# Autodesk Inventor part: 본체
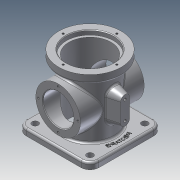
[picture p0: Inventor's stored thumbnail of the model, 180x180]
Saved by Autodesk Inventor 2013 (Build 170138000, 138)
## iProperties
Created: 2021-03
Part Number: 본체
Material: 알루미늄 6061
Document SubType Name: Modeling
Designer: a
Density: 2.71 g/cm^3
Mass: 833.809 g
Surface Area: 863.886 cm^2
Volume: 307.678 cm^3
Author: a
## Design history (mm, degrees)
sketch "스케치2"
  geometry: L1 (0, 55.5)-(0, -55.5); L2 (0, 55.5)-(-38, 55.5); L3 (-38, 55.5)-(-38, -55.5); L4 (-38, -55.5)-(0, -55.5); 2 further points
  constraints: 8 end point, 3 perpendicular, 1 coincident, 1 midpoint, 1 vertical
  dimensions: "d2" = 111 distance of L1.start L1.end; "d3" = 38 distance of L1.start L2.end
revolve "회전1" sketch "스케치2" stored, may be unused: angle "d4" = 90 deg
sketch "스케치3"
  geometry: C1 r 38 at (0, 0) reference; 1 further point
  constraints: 1 coincident
hole "구멍1" sketch "스케치3" at (0, 0) diameter "d5" = 66; stored, may be unused: countersink angle "d9" = 90 deg, drill point angle "d11" = 118 deg; dims "d6" = 6, "d7" = 74, "d8" = 7, "d10" = 8
sketch "스케치4"
  geometry: C1 r 38 at (0, 0) reference; C2 r 49 at (0, 0)
  constraints: 1 centre point, 1 coincident
  dimensions: "d12" = 98 diameter of C2
extrude "돌출1" join sketch "스케치4" distance "d13" = 13; taper "d14" = 0 deg
node "작업 평면1"
sketch "스케치6"
  geometry: L1 (38, -55.5)-(-38, -55.5) reference; L2 (0, -55.5)-(0, -1.5); C1 r 35 at (0, -1.5); 1 further point
  constraints: 2 end point, 1 centre point, 1 coincident, 1 midpoint, 1 perpendicular
  dimensions: "d88" = 54 distance of L2.start L2.end; "d89" = 70 diameter of C1
extrude "돌출2" join sketch "스케치6" stored distance "d17" = 13; taper "d18" = 0 deg
sketch "스케치9"
  geometry: L1 (43, -57)-(-43, -57); L2 (-57, -43)-(-57, 43); L3 (-43, 57)-(43, 57); L4 (57, 43)-(57, -43); L5 (57, -57)-(-57, 57); L6 (-57, -57)-(57, 57); C1 r 38 at (0, 0) reference; A1 r 14 centre (-43, 43) between (-43, 57) and (-57, 43); A2 r 14 centre (43, 43) between (57, 43) and (43, 57); A3 r 14 centre (-43, -43) between (-57, -43) and (-43, -57); A4 r 14 centre (43, -43) between (43, -57) and (57, -43)
  constraints: 12 end point, 8 point on circle, 8 point on line, 8 tangent, 4 centre point, 3 equal radius, 2 midpoint, 2 parallel, 1 horizontal, 1 perpendicular
  dimensions: "d34" = 114 distance of L5.end L6.end; "d35" = 114 distance of L6.start L5.end; "d36" = 14 radius of A1
extrude "돌출4" join sketch "스케치9" distance "d37" = 10; taper "d38" = 0 deg
sketch "스케치10"
  geometry: A1 r 14 centre (43, -43) between (43, -57) and (57, -43) reference; A2 r 14 centre (43, 43) between (57, 43) and (43, 57) reference; A3 r 14 centre (-43, 43) between (-43, 57) and (-57, 43) reference; A4 r 14 centre (-43, -43) between (-57, -43) and (-43, -57) reference; 4 further points
  constraints: 4 coincident
hole "구멍3" sketch "스케치10" at (-43, 43), (43, 43), (43, -43), (-43, -43) diameter "d39" = 10; stored, may be unused: countersink angle "d43" = 90 deg, drill point angle "d45" = 0 deg; dims "d40" = 6, "d41" = 74, "d42" = 7, "d44" = 8
node "작업 평면3"
sketch "스케치11"
  geometry: L1 (-14.5, -7)-(14.5, -7); L2 (14.5, -7)-(14.5, 7); L3 (14.5, 7)-(-14.5, 7); L4 (-14.5, 7)-(-14.5, -7); L5 (-14.5, -7)-(14.5, 7); L6 (14.5, -7)-(-14.5, 7); 1 further point
  constraints: 12 end point, 2 midpoint, 2 parallel, 1 horizontal, 1 perpendicular
  dimensions: "d50" = 29 distance of L3.end L2.end; "d52" = 14 distance of L1.end L2.end
extrude "돌출5" join sketch "스케치11" stored distance "d53" = 10; taper "d54" = 0 deg
feature "면 기울기1" dims angle "d55" = 15 deg
feature "면 기울기2" dims angle "d56" = 15 deg
sketch "스케치12"
  geometry: L1 (7, 14.5)-(-7, 14.5) reference; L2 (-7, -14.5)-(7, -14.5) reference; 3 further points
  constraints: 2 horizontal alignment, 2 midpoint, 4 other
extrude "돌출6" join sketch "스케치12" stored distance "d61" = 0; taper "d62" = 15 deg
sketch "스케치13"
  geometry: A1 r 7 centre (0, -14.5) between (-7, -14.5) and (7, -14.5) reference; A2 r 7 centre (0, 14.5) between (7, 14.5) and (-7, 14.5) reference; 3 further points
  constraints: 2 coincident
hole "구멍4" sketch "스케치13" at (0, 14.5), (0, -14.5) diameter "d63" = 4.134; stored, may be unused: countersink angle "d67" = 90 deg, drill point angle "d69" = 118 deg; dims "d64" = 8, "d65" = 74, "d66" = 7, "d68" = 10
sketch "스케치14"
  geometry: L1 (0, 0)-(0, 42); C1 r 37 at (0, 0) reference; 1 further point
  constraints: 2 end point, 1 coincident, 1 vertical
  dimensions: "d70" = 42 distance of L1.start L1.end
hole "구멍5" sketch "스케치14" at (0, 42) diameter "d71" = 3.242; stored, may be unused: countersink angle "d75" = 90 deg, drill point angle "d77" = 118 deg; dims "d72" = 6, "d73" = 74, "d74" = 7, "d76" = 8
fillet "모깎기1" dims "d81" = 3
chamfer "모따기1" distance "d82" = 1; stored, may be unused: second distance "d83" = 2, angle "d84" = 45 deg
sketch "스케치15"
  geometry: C1 r 41 at (0, 0) reference; C2 r 50 at (0, 0)
  constraints: 1 centre point, 1 coincident, 1 other
  dimensions: "d85" = 100 diameter of C2
feature "엠보싱1" sketch "스케치15" dims "d18" = 0, "d86" = 0.5, "d87" = 0
sketch "스케치16"
  geometry: L1 (0, 0)-(0, 31); C1 r 35 at (0, 0) reference; 2 further points
  constraints: 2 end point, 1 coincident, 1 vertical
  dimensions: "d90" = 31 distance of L1.start L1.end
hole "구멍6" sketch "스케치16" at (0, 31) diameter "d91" = 3.242; stored, may be unused: countersink angle "d95" = 90 deg, drill point angle "d97" = 118 deg; dims "d92" = 6, "d93" = 74, "d94" = 7, "d96" = 8
sketch "스케치17"
  geometry: C1 r 35 at (0, 0) reference; C2 r 24 at (0, 0); 1 further point
  constraints: 1 centre point, 1 coincident
  dimensions: "d101" = 48 diameter of C2
extrude "돌출7" cut sketch "스케치17" stored distance "d102" = 10; taper "d103" = 0 deg
chamfer "모따기2" distance "d104" = 1; stored, may be unused: second distance "d105" = 2, angle "d106" = 45 deg
fillet "모깎기2" dims "d107" = 3
node "솔리드1"
mirror "대칭1"
pattern_circular "원형 패턴2" dims angle "d79" = 360 deg
pattern_circular "원형 패턴3" dims angle "d99" = 360 deg
mirror "대칭2"
other parameters: "d46" = 55
